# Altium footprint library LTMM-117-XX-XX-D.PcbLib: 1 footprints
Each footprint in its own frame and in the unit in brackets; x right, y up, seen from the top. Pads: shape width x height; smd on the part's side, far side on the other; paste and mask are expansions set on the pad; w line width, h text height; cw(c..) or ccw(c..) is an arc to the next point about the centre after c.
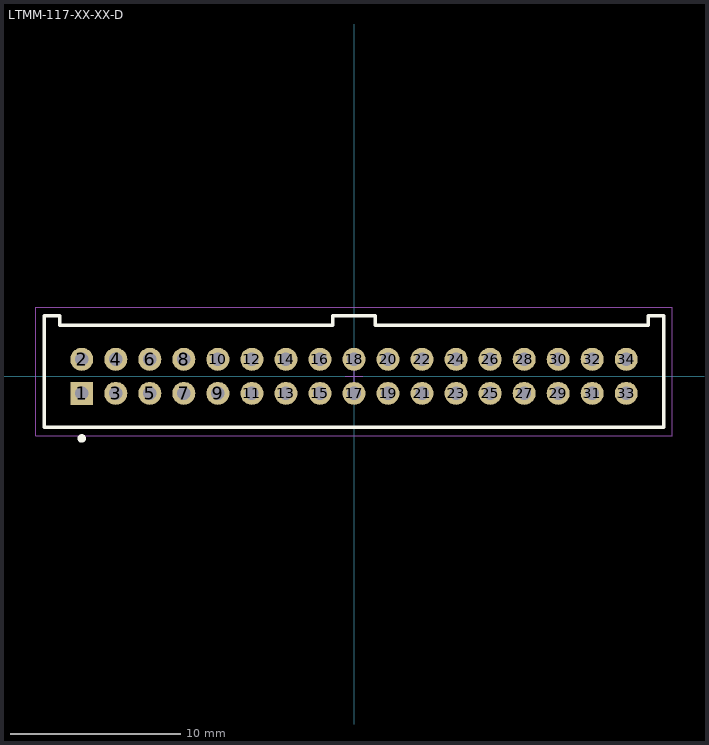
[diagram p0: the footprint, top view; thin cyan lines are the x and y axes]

## LTMM-117-XX-XX-D [mm] "2.00mm pitch, 34 pin, header; vertical, double row, PTH"
height 4.8
pads (34):
  rect 1.35x1.35 / inner round 1.35 / far side rect 1.35x1.35 hole 0.8 mask+0: 1(-16,-1)
  round 1.35 hole 0.8 mask+0: 2(-16,1) 3(-14,-1) 4(-14,1) 5(-12,-1) 6(-12,1) 7(-10,-1) 8(-10,1) 9(-8,-1) 10(-8,1) 11(-6,-1) 12(-6,1) 13(-4,-1) 14(-4,1) 15(-2,-1) 16(-2,1) 17(0,-1) 18(0,1) 19(2,-1) 20(2,1) 21(4,-1) 22(4,1) 23(6,-1) 24(6,1) 25(8,-1) 26(8,1) 27(10,-1) 28(10,1) 29(12,-1) 30(12,1) 31(14,-1) 32(14,1) 33(16,-1) 34(16,1)
Top Overlay:
  circle w0.25: c-16,-3.65 r0.125
  lines w0.2: -18.2,-3 18.2,-3 18.2,3.55 17.3,3.55 17.3,3 1.25,3 1.25,3.55 -1.25,3.55 -1.25,3 -17.3,3 -17.3,3.55 -18.2,3.55 -18.2,-3
Mechanical 12:
  lines w0.001: -18.2,-3 18.2,-3 18.2,3.55 17.3,3.55 17.3,3 1.25,3 1.25,3.55 -1.25,3.55 -1.25,3 -17.3,3 -17.3,3.55 -18.2,3.55 -18.2,-3
Mechanical 13:
  lines w0.1: -18.2,-3 18.2,-3 18.2,3.55 17.3,3.55 17.3,3 1.25,3 1.25,3.55 -1.25,3.55 -1.25,3 -17.3,3 -17.3,3.55 -18.2,3.55 -18.2,-3
  text ".Designator" at 0.254,0.254 h1.52
Mechanical 15:
  lines w0.05: -0.5,0 0.5,0 ; 0,-0.5 0,0.5 ; -18.7,-3.5 18.7,-3.5 18.7,4.05 -18.7,4.05 -18.7,-3.5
